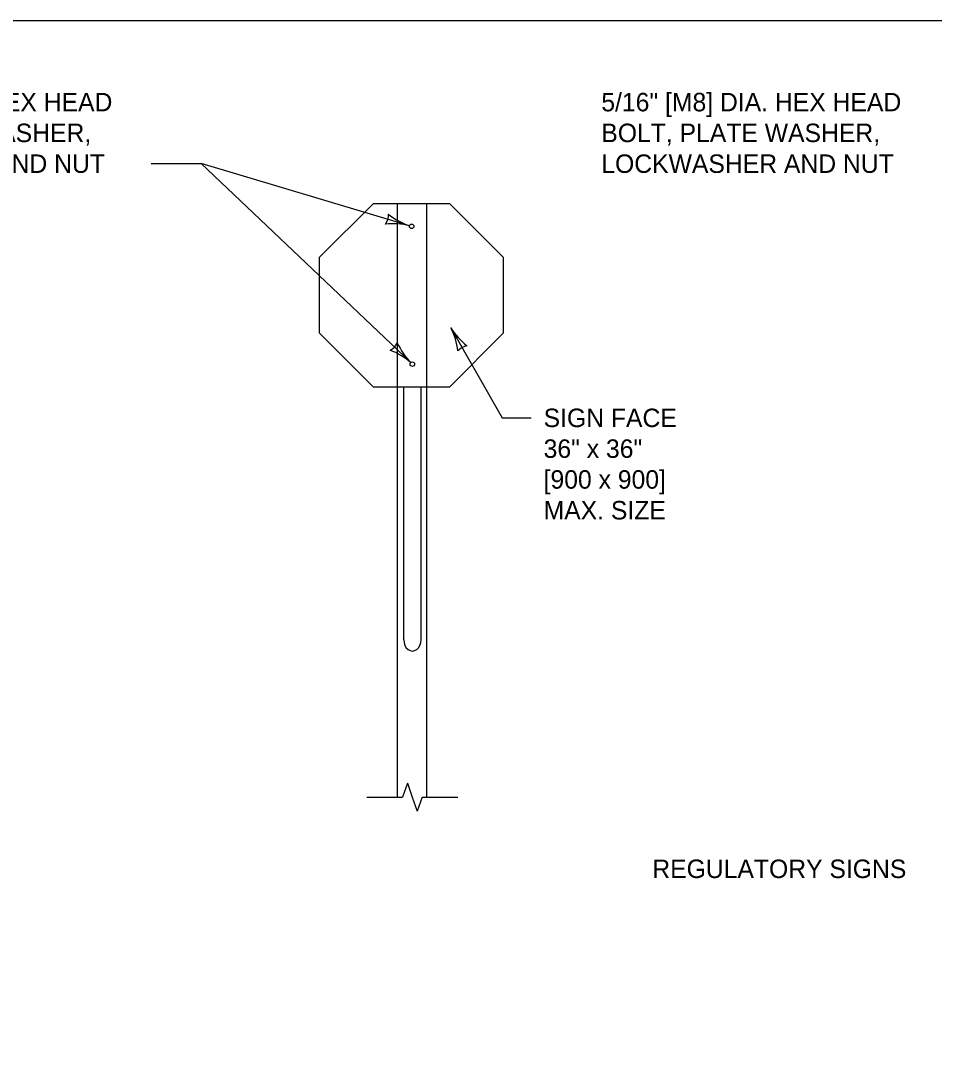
# Model space of a CAD drawing. Extents: x 49991.4 to 50021, y 49987.6 to 50011.4.
# Drawn here: x 50008.843 to 50011.809, y 49995.645 to 49998.999 of the extents above; entities that cross this region are included whole.
import ezdxf

# ---------------------------------------------------------------- set-up
doc = ezdxf.new("R2010")
doc.units = 0
for name, color, linetype in [('Level 1', 7, 'Continuous'), ('Level 2', 7, 'Continuous'), ('Level 3', 7, 'Continuous'), ('Level 4', 7, 'Continuous'), ('Level 6', 7, 'Continuous')]:
    doc.layers.add(name, color=color, linetype=linetype)

msp = doc.modelspace()

# ---------------------------------------------------------------- linework, layer by layer
at = {"layer": 'Level 1'}
for p, q in [((50009.8134, 49998.2306), (50009.9881, 49998.4053)), ((50009.9881, 49998.4053), (50010.235, 49998.4053)), ((50010.235, 49998.4053), (50010.4096, 49998.2306)), ((50009.8134, 49997.9837), (50009.8134, 49998.2306)), ((50010.4096, 49998.2306), (50010.4096, 49997.9837)), ((50009.9881, 49997.8091), (50009.8134, 49997.9837)), ((50010.4096, 49997.9837), (50010.235, 49997.8091)), ((50010.235, 49997.8091), (50009.9881, 49997.8091)), ((50010.0667, 49996.4774), (50010.0667, 49997.8091)), ((50010.0865, 49996.9886), (50010.0865, 49997.8091)), ((50010.1425, 49996.9886), (50010.1425, 49997.8091)), ((50010.1619, 49996.4774), (50010.1619, 49997.8091))]:
    msp.add_line(p, q, dxfattribs=at)
msp.add_lwpolyline([(49999.3835, 49998.9992), (50016.7501, 49998.9992), (50016.7501, 49987.7988), (49999.3835, 49987.7988)], close=True, dxfattribs=at)
for centre in [(50010.1122, 49998.3311), (50010.1144, 49997.8836)]:
    msp.add_circle(centre, 0.0072, dxfattribs=at)
msp.add_ellipse((50010.1145, 49996.9886), major_axis=(0, -0.0368), ratio=0.761048, start_param=4.712389, end_param=7.853982, dxfattribs=at)
at = {"layer": 'Level 3'}
for p, q in [((50009.2659, 49998.5347), (50009.4289, 49998.5347)), ((50010.1053, 49998.3331), (50009.4289, 49998.5347)), ((50010.1092, 49997.8885), (50009.4289, 49998.5347)), ((50010.2393, 49998.0013), (50010.4058, 49997.7091)), ((50010.4058, 49997.7091), (50010.5006, 49997.7091))]:
    msp.add_line(p, q, dxfattribs=at)
for centre, radius, start, end in [((50009.9823, 49998.3692), 0.0548, 325.7923, 1.5147), ((50010.1766, 49998.5437), 0.2223, 231.1095, 251.293), ((50010.0508, 49998.1066), 0.233, 76.4808, 95.7306), ((50010.0418, 49997.8993), 0.2223, 7.1312, 27.3147), ((50010.4358, 49998.1265), 0.233, 212.5025, 231.7523), ((50010.0162, 49997.9768), 0.0548, 298.6131, 334.3355), ((50009.9572, 49997.7119), 0.233, 49.3016, 68.5515), ((50010.2688, 49998.0433), 0.2223, 203.9303, 224.1138), ((50010.3028, 49997.8899), 0.0548, 101.814, 137.5363)]:
    msp.add_arc(centre, radius, start, end, dxfattribs=at)
at = {"layer": 'Level 4'}
for p, q in [((50010.0667, 49997.806), (50010.0667, 49998.4053)), ((50010.1619, 49997.806), (50010.1619, 49998.4053))]:
    msp.add_line(p, q, dxfattribs=at)
at = {"layer": 'Level 6'}
for p, q in [((50010.0981, 49996.5231), (50010.0819, 49996.4774)), ((50010.0981, 49996.5231), (50010.1143, 49996.4774)), ((50009.9667, 49996.4774), (50010.0819, 49996.4774)), ((50010.1143, 49996.4774), (50010.1305, 49996.4317)), ((50010.1467, 49996.4774), (50010.1305, 49996.4317)), ((50010.1467, 49996.4774), (50010.2619, 49996.4774))]:
    msp.add_line(p, q, dxfattribs=at)

# ---------------------------------------------------------------- texts
at = {"layer": 'Level 2'}
for s, p in [('5/16" [M8] DIA. HEX HEAD', (50008.1667, 49998.7047)), ('5/16" [M8] DIA. HEX HEAD', (50010.7279, 49998.7047)), ('BOLT, PLATE WASHER,', (50008.1667, 49998.6047)), ('BOLT, PLATE WASHER,', (50010.7279, 49998.6047)), ('LOCKWASHER AND NUT', (50008.1667, 49998.5047)), ('LOCKWASHER AND NUT', (50010.7279, 49998.5047)), ('SIGN FACE', (50010.5406, 49997.6791)), ('36" x 36"', (50010.5406, 49997.5791)), ('[900 x 900]', (50010.5406, 49997.4791)), ('MAX. SIZE', (50010.5406, 49997.3791)), ('REGULATORY SIGNS', (50010.8934, 49996.2144))]:
    msp.add_text(s, height=0.06, dxfattribs=at).set_placement(p)

doc.saveas('drawing.dxf')
